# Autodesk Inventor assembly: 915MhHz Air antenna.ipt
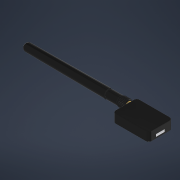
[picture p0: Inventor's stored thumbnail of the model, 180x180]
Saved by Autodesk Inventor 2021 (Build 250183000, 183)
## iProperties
Created: 2021-07
Part Number: 915MhHz Air antenna.ipt
Document SubType Name: Assembly
Designer: Fish
Author: Fish
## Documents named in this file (5)
- S:\Inventor Files\UAS\Peuco\Seabat\915MhHz Air antenna.ipt.iam
- S:\Inventor Files\UAS\Peuco\Seabat\915MhHz Air.ipt
- S:\Inventor Files\UAS\Peuco\Seabat\Antenna body.ipt
- S:\Inventor Files\UAS\Peuco\Seabat\Antenna base.ipt
- S:\Inventor Files\UAS\Peuco\Seabat\Threads.ipt
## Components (4 placed, 4 different names)
1. 915MhHz Air:1 — Mate:5, Mate:6, Angle:1
2. Antenna body:1 — Mate:1, Mate:2, Cylindrical:1
3. Antenna base:1 — Mate:1, Mate:2, Mate:3, Mate:4, Angle:1, Cylindrical:1
4. Threads:1 — Mate:3, Mate:4, Mate:5, Mate:6
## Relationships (8: Mate 6, Angle 1, CylindricalJoint 1)
- Mate:1: Antenna body:1 ↔ Antenna base:1
- Mate:2: Antenna body:1 ↔ Antenna base:1
- Mate:3: Antenna base:1 ↔ Threads:1
- Mate:4: Antenna base:1 ↔ Threads:1
- Mate:5: 915MhHz Air:1 ↔ Threads:1
- Mate:6: 915MhHz Air:1 ↔ Threads:1
- Angle:1: 915MhHz Air:1 ↔ Antenna base:1
- Cylindrical:1: Antenna body:1 ↔ Antenna base:1
